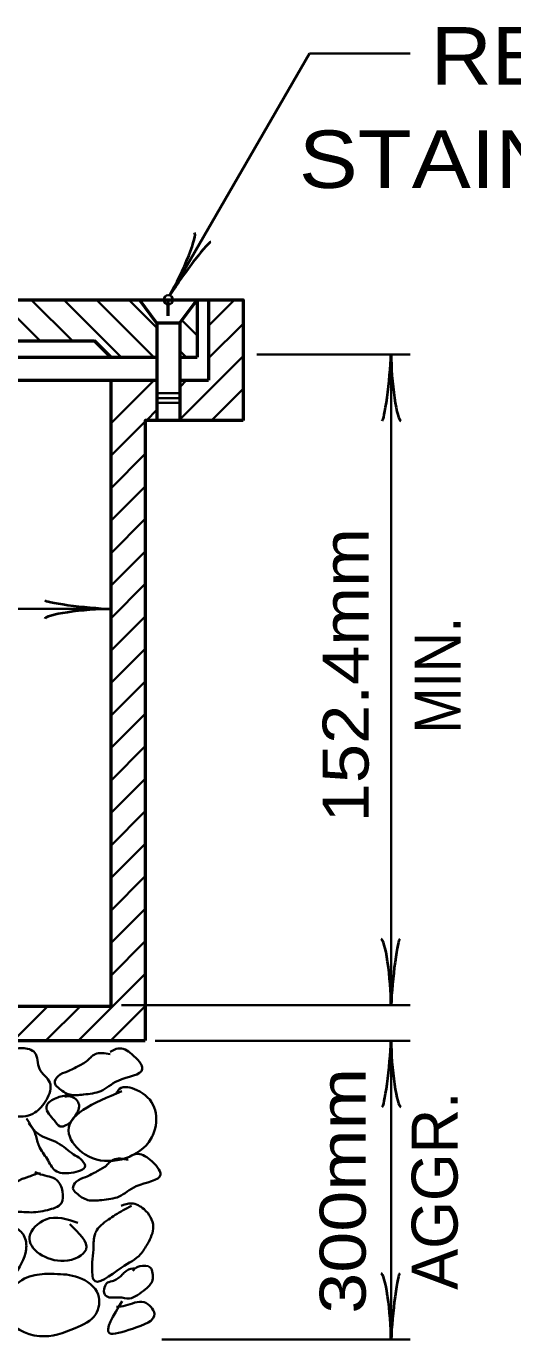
# Model space of a CAD drawing. Extents: x 442 to 1297, y -1132 to -588.
# Drawn here: x 1093.8 to 1119.2, y -929 to -860.4 of the extents above; entities that cross this region are included whole.
import ezdxf
from ezdxf.enums import TextEntityAlignment as Align

# ---------------------------------------------------------------- set-up
doc = ezdxf.new("R2010")
doc.units = 0
doc.header["$LTSCALE"] = 0.96
doc.header["$PDMODE"] = 32
doc.header["$PDSIZE"] = 0.48
doc.layers.add('1', color=7, linetype='Continuous', lineweight=35)

msp = doc.modelspace()

# ---------------------------------------------------------------- linework, layer by layer
at = {"layer": '1'}
for p, q in [((1101.3415, -874.4112), (1108.6256, -861.7948)), ((1108.6256, -861.7948), (1113.8741, -861.7948)), ((1094.5578, -876.8132), (1092.4063, -874.6617)), ((1096.2548, -876.8132), (1094.1033, -874.6617)), ((1098.8003, -877.6617), (1095.8003, -874.6617)), ((1100.4973, -877.6617), (1097.4973, -874.6617)), ((1100.654, -876.1214), (1099.1943, -874.6617)), ((1103.354, -876.02), (1104.7122, -874.6617)), ((1102.754, -876.5244), (1101.9557, -875.7261)), ((1103.354, -877.7172), (1105.154, -875.917)), ((1101.8066, -880.9617), (1105.154, -877.6141)), ((1102.1943, -877.6617), (1101.854, -877.3214)), ((1105.8758, -877.5252), (1113.8811, -877.5252)), ((1112.8799, -911.5073), (1112.8799, -877.5252)), ((1098.254, -881.1203), (1100.5124, -878.8617)), ((1101.854, -879.2172), (1102.2094, -878.8617)), ((1100.6889, -879.5389), (1101.8915, -879.5389)), ((1103.5036, -880.9617), (1105.154, -879.3112)), ((1100.6692, -879.7962), (1101.8718, -879.7962)), ((1100.6692, -880.0517), (1101.8718, -880.0517)), ((1098.254, -882.8173), (1100.054, -881.0172)), ((1100.1095, -880.9617), (1100.654, -880.4171)), ((1098.254, -884.5144), (1100.054, -882.7143)), ((1098.254, -886.2116), (1100.054, -884.4115)), ((1098.254, -887.9087), (1100.054, -886.1086)), ((1098.254, -889.6057), (1100.054, -887.8057)), ((1098.254, -891.3029), (1100.054, -889.5028)), ((1049.354, -890.8139), (1098.254, -890.8139)), ((1098.254, -892.9999), (1100.054, -891.1999)), ((1098.254, -894.6971), (1100.054, -892.897)), ((1098.254, -896.3951), (1100.054, -894.5951)), ((1098.254, -898.0913), (1100.054, -896.2912)), ((1098.254, -899.7884), (1100.054, -897.9883)), ((1098.254, -901.4854), (1100.054, -899.6853)), ((1098.254, -903.1826), (1100.054, -901.3825)), ((1098.254, -904.8796), (1100.054, -903.0795)), ((1098.254, -906.5768), (1100.054, -904.7767)), ((1098.254, -908.2738), (1100.054, -906.4737)), ((1098.254, -909.9711), (1100.054, -908.171)), ((1096.5605, -913.3617), (1100.054, -909.868)), ((1093.1664, -913.3617), (1094.9662, -911.5617)), ((1094.8636, -913.3617), (1096.6634, -911.5617)), ((1098.2576, -913.3617), (1100.054, -911.5652)), ((1098.8133, -911.5073), (1113.8811, -911.5073)), ((1100.5679, -913.379), (1113.8811, -913.379)), ((1112.8799, -928.979), (1112.8799, -913.379)), ((1100.919, -928.979), (1113.8811, -928.979))]:
    msp.add_line(p, q, dxfattribs=at)
at = {"layer": '1', "lineweight": 53}
for p, q in [((1100.6448, -875.8617), (1099.7448, -874.6617)), ((1101.254, -875.5017), (1101.254, -874.6617)), ((1101.854, -875.8617), (1102.754, -874.6617)), ((1102.754, -874.6617), (1102.754, -877.6617)), ((1103.354, -874.6617), (1103.354, -878.8617)), ((1100.654, -875.8617), (1100.654, -880.9617)), ((1100.654, -875.8617), (1101.854, -875.8617)), ((1101.854, -875.8617), (1101.854, -880.9617)), ((1050.2025, -876.8132), (1097.4055, -876.8132)), ((1098.254, -877.6617), (1097.4055, -876.8132)), ((1046.954, -877.6617), (1100.6607, -877.6617)), ((1101.8042, -877.6617), (1102.754, -877.6617)), ((1046.954, -878.8617), (1100.6271, -878.8617)), ((1098.254, -878.8617), (1098.254, -911.5617)), ((1101.821, -878.8617), (1103.354, -878.8617)), ((1049.354, -911.5617), (1098.254, -911.5617))]:
    msp.add_line(p, q, dxfattribs=at)
for points in [[(1042.454, -874.6617), (1105.154, -874.6617), (1105.154, -880.9617)], [(1047.554, -880.9617), (1047.554, -913.3617), (1100.054, -913.3617)], [(1105.154, -880.9617), (1100.054, -880.9617), (1100.054, -913.3617)]]:
    msp.add_lwpolyline(points, dxfattribs=at)
at = {"layer": '1', "lineweight": 40}
for centre, major_axis, ratio, start_param, end_param in [((1101.7091, -873.1114), (-0.9091, -1.9494), 0.122415, 0.8963533, 3.1415927), ((1102.2337, -873.3737), (1.2364, 1.72), 0.07063, 6.2823074, 8.5597026), ((1112.626, -878.8698), (-0.2108, -2.1077), 0.07063, 6.2823074, 8.5597026), ((1112.626, -878.8698), (-0.2108, -2.1077), 0.07063, 6.2823074, 8.5597026), ((1113.2115, -878.8346), (-0.1874, 2.1428), 0.122415, 0.8963533, 3.1415927), ((1113.2115, -878.8346), (-0.1874, 2.1428), 0.122415, 0.8963533, 3.1415927), ((1096.9094, -890.56), (2.1077, -0.2108), 0.07063, 3.1407148, 5.41811), ((1096.9446, -891.1455), (2.1428, 0.1874), 0.122415, 0.8963533, 3.1415927), ((1112.5483, -910.1979), (0.1874, -2.1428), 0.122415, 0.8963533, 3.1415927), ((1112.5483, -910.1979), (0.1874, -2.1428), 0.122415, 0.8963533, 3.1415927), ((1113.1338, -910.1627), (0.2108, 2.1077), 0.07063, 6.2823074, 8.5597026), ((1113.1338, -910.1627), (0.2108, 2.1077), 0.07063, 6.2823074, 8.5597026), ((1112.626, -914.7236), (-0.2108, -2.1077), 0.07063, 6.2823074, 8.5597026), ((1112.626, -914.7236), (-0.2108, -2.1077), 0.07063, 6.2823074, 8.5597026), ((1113.2115, -914.6884), (-0.1874, 2.1428), 0.122415, 0.8963533, 3.1415927), ((1113.2115, -914.6884), (-0.1874, 2.1428), 0.122415, 0.8963533, 3.1415927), ((1112.5483, -927.6696), (0.1874, -2.1428), 0.122415, 0.8963533, 3.1415927), ((1113.1338, -927.6344), (0.2108, 2.1077), 0.07063, 6.2823074, 8.5597026)]:
    msp.add_ellipse(centre, major_axis=major_axis, ratio=ratio, start_param=start_param, end_param=end_param, dxfattribs=at)
at = {"layer": '1'}
for points in [[(1093.2663, -913.8754), (1093.146, -914.2964), (1092.6648, -915.1986), (1091.943, -916.2212), (1091.4017, -916.4016), (1091.1009, -916.4016), (1093.2061, -917.3039), (1094.2888, -917.1234), (1094.8903, -916.4618), (1095.0707, -915.5595), (1094.5294, -914.8378), (1094.2888, -913.9957), (1093.6272, -913.7551), (1092.9655, -913.8152)], [(1098.2106, -914.0738), (1097.4287, -914.0738), (1097.2482, -914.1941), (1097.0678, -914.3745), (1096.5866, -914.6752), (1095.9851, -914.976), (1095.5039, -915.2166), (1095.3235, -915.5775), (1095.5039, -915.8181), (1096.1054, -916.179), (1096.8272, -916.179), (1097.7294, -915.9985), (1098.6317, -915.4572), (1099.8948, -914.8557), (1099.3534, -914.0738), (1098.6317, -913.773), (1098.2106, -913.9535)], [(1098.8328, -916.0073), (1096.0659, -918.2328), (1096.908, -919.3154), (1100.0959, -918.8343), (1100.5169, -918.1125), (1100.5169, -916.8493), (1099.6147, -915.9471), (1098.7125, -915.887), (1098.532, -916.1276)], [(1095.973, -916.2221), (1095.3114, -916.4026), (1094.8904, -916.8236), (1095.0107, -917.1845), (1095.3114, -917.5454), (1095.6121, -917.8462), (1095.9129, -917.786), (1096.3941, -917.3048), (1096.5745, -916.6432), (1096.1535, -916.2823), (1095.8527, -916.2823)], [(1093.9641, -917.6813), (1094.4453, -918.2227), (1095.4678, -918.7038), (1096.3099, -919.3053), (1096.6708, -919.5459), (1096.9114, -919.9068), (1096.1896, -920.2677), (1095.3475, -920.1474), (1094.9265, -919.5459), (1094.5055, -918.8843), (1094.325, -918.2828), (1093.8438, -917.4407)], [(1099.1625, -919.5868), (1098.3806, -919.5868), (1098.2001, -919.7071), (1098.0197, -919.8875), (1097.5385, -920.1882), (1096.937, -920.489), (1096.4558, -920.7296), (1096.2754, -921.0905), (1096.4558, -921.3311), (1097.0573, -921.692), (1097.7791, -921.692), (1098.6813, -921.5115), (1099.5836, -920.9702), (1100.8467, -920.3687), (1100.3053, -919.5868), (1099.5836, -919.286), (1099.1625, -919.4665)], [(1094.5878, -920.2892), (1094.287, -920.3494), (1093.9863, -920.4697), (1093.8059, -920.5298), (1093.6254, -920.59), (1093.1442, -920.8907), (1092.6029, -921.4321), (1092.1818, -921.9734), (1092.3021, -922.3945), (1093.2044, -922.3343), (1093.9863, -922.3343), (1094.9487, -922.214), (1095.6705, -921.8531), (1095.7306, -921.2516), (1095.4299, -920.6501), (1094.5878, -920.3494), (1094.287, -920.2291)], [(1099.3269, -921.9918), (1098.4848, -922.473), (1098.1239, -922.7136), (1097.4623, -923.3752), (1097.4021, -923.5556), (1097.342, -924.2774), (1097.2818, -924.9391), (1097.2818, -925.4804), (1097.342, -925.8413), (1098.7856, -925.2398), (1099.8081, -924.518), (1100.169, -923.9767), (1100.4697, -923.0745), (1099.9885, -922.1722), (1099.3269, -921.8715), (1098.7856, -921.9918)], [(1096.5364, -922.8855), (1094.8522, -922.7051), (1094.0101, -923.6073), (1095.8146, -924.8704), (1096.9574, -924.2689), (1096.1153, -922.9456)], [(1092.3304, -923.308), (1091.8492, -923.2479), (1091.2478, -923.4884), (1091.0673, -923.9696), (1090.7666, -924.8719), (1090.7064, -925.1125), (1090.5861, -925.4734), (1090.526, -925.8342), (1090.947, -926.2553), (1091.8492, -926.2553), (1092.5109, -926.4357), (1093.1725, -925.714), (1093.8342, -924.2704), (1093.7139, -923.5486), (1093.2327, -923.1276), (1092.6913, -923.0674), (1092.0297, -923.3681)], [(1092.9579, -926.6357), (1092.8376, -927.7785), (1094.5218, -928.8011), (1096.3864, -928.38), (1097.4691, -927.6582), (1097.5894, -926.6357), (1096.5669, -925.7335), (1095.3037, -925.553), (1094.2812, -925.6132), (1093.7399, -925.7936), (1092.8376, -926.6357)], [(1099.5251, -925.272), (1099.4048, -925.272), (1098.9837, -925.4525), (1098.8033, -925.6329), (1098.3221, -925.9337), (1098.0214, -926.054), (1097.9612, -926.1743), (1097.9011, -926.5352), (1098.0214, -926.7156), (1098.683, -926.7758), (1099.2243, -926.8359), (1099.6454, -926.6555), (1100.0664, -926.3547), (1100.4273, -925.8735), (1100.4273, -925.5126), (1100.307, -925.2119), (1099.7657, -925.1517), (1099.5852, -925.2119), (1099.4048, -925.3923)], [(1098.8453, -926.9692), (1098.1836, -928.6533), (1099.3866, -928.4127), (1100.5294, -927.6308), (1099.9881, -927.0293), (1099.0257, -927.2097), (1098.5445, -927.2699)]]:
    msp.add_spline(points, degree=3, dxfattribs=at)
msp.add_point((1101.254, -874.6617), dxfattribs=at)

# ---------------------------------------------------------------- texts
for s, width, p in [('RECESSED MONEL OR', 1.1, (1139.4718, -863.4159)), ('STAINLESS STEEL SCREWS', 1.15, (1139.4719, -868.8159))]:
    msp.add_text(s, height=3, dxfattribs=dict(at, width=width)).set_placement(p, align=Align.CENTER)
for s, width, p in [('152.4mm', 1.15, (1111.7091, -894.2769)), ('MIN.', 0.9, (1116.5091, -894.277)), ('300mm', 1.2, (1111.5564, -921.2112))]:
    msp.add_text(s, height=2.4, rotation=90, dxfattribs=dict(at, width=width)).set_placement(p, align=Align.CENTER)
msp.add_text('AGGR.', height=2.4, rotation=90, dxfattribs=at).set_placement((1116.3564, -921.2112), align=Align.CENTER)

doc.saveas('drawing.dxf')
